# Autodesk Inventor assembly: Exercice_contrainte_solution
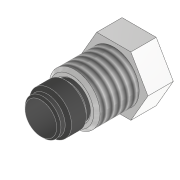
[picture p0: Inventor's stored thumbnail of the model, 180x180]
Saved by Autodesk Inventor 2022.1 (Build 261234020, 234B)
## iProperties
Created: 2021-07
Part Number: Exercice_contrainte_solution
Document SubType Name: Assembly
Designer: Fabian
Author: Fabian
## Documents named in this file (3)
- C:\Users\fabia\Mon Drive\01_Giup\01_Clients\07_ENI\Manuscrit\Fichiers_exercice\Chapitre_06\Exercice_contrainte\Exercice_contrainte_solution.iam
- C:\Users\fabia\Mon Drive\01_Giup\01_Clients\07_ENI\Manuscrit\Fichiers_exercice\Chapitre_06\Exercice_contrainte\Vis.ipt
- C:\Users\fabia\Mon Drive\01_Giup\01_Clients\07_ENI\Manuscrit\Fichiers_exercice\Chapitre_06\Exercice_contrainte\Bague.ipt
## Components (2 placed, 2 different names)
1. Vis:1 — Logement:1
2. Bague:1 — Logement:1
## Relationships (1: Insert 1)
- Logement:1 [Insert]: Vis:1 ↔ Bague:1
